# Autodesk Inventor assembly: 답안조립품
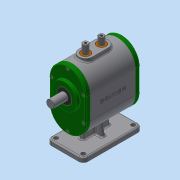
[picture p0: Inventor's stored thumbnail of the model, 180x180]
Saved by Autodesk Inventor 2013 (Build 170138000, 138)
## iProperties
Created: 2018-10
Part Number: 답안조립품
Document SubType Name: Assembly
Designer: Administrator
Author: Administrator
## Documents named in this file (15)
- C:\Users\Administrator\Desktop\381007V1019\답안조립품.iam
- C:\Users\Administrator\Desktop\381007V1019\본체.ipt
- C:\Users\Administrator\Desktop\381007V1019\가변스프링1.ipt
- C:\Users\Administrator\Desktop\381007V1019\가변스프링2.ipt
- C:\Users\Administrator\Desktop\381007V1019\뒤커버.ipt
- C:\Users\Administrator\Desktop\381007V1019\메인축.ipt
- C:\Users\Administrator\Desktop\381007V1019\베어링 608.ipt
- C:\Users\Administrator\Desktop\381007V1019\베어링 6003.ipt
- C:\Users\Administrator\Desktop\381007V1019\볼트 M4.ipt
- C:\Users\Administrator\Desktop\381007V1019\부시.ipt
- C:\Users\Administrator\Desktop\381007V1019\서브축.ipt
- C:\Users\Administrator\Desktop\381007V1019\슬라이더.ipt
- C:\Users\Administrator\Desktop\381007V1019\앞커버.ipt
- C:\Users\Administrator\Desktop\381007V1019\오일실 8 22 7.ipt
- C:\Users\Administrator\Desktop\381007V1019\오일실 17 32 8.ipt
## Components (2 placed, 2 different names)
1. 가변스프링1:1
2. 가변스프링2:1
